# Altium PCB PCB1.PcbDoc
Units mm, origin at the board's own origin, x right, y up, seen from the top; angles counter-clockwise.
Board outline 20 x 15 mm, 2 copper layers (Top Layer, Bottom Layer); 3 components, 0 nets, 4 pads, 0 vias.
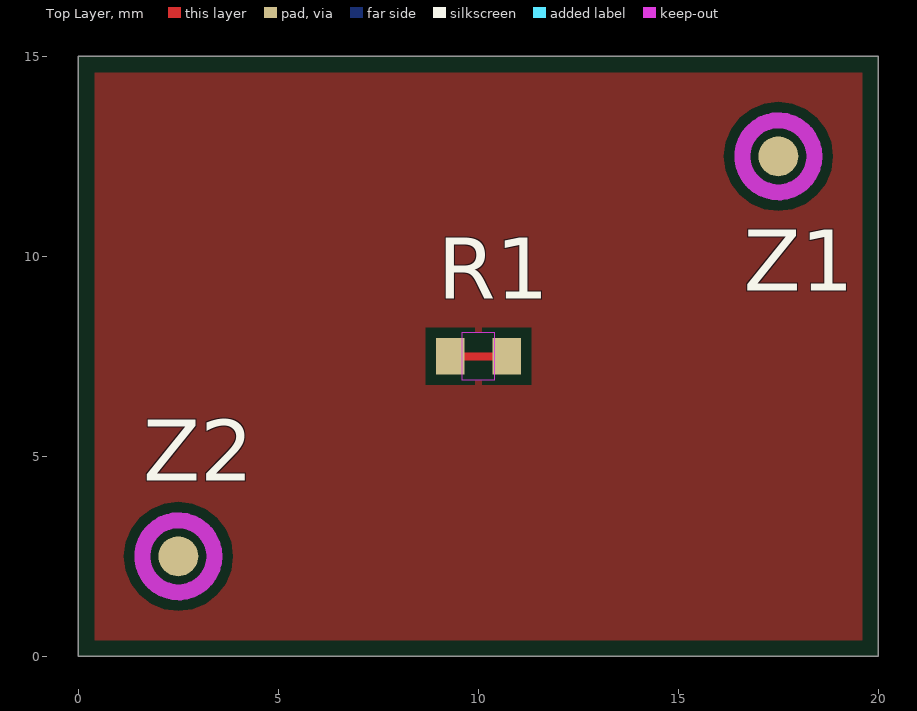
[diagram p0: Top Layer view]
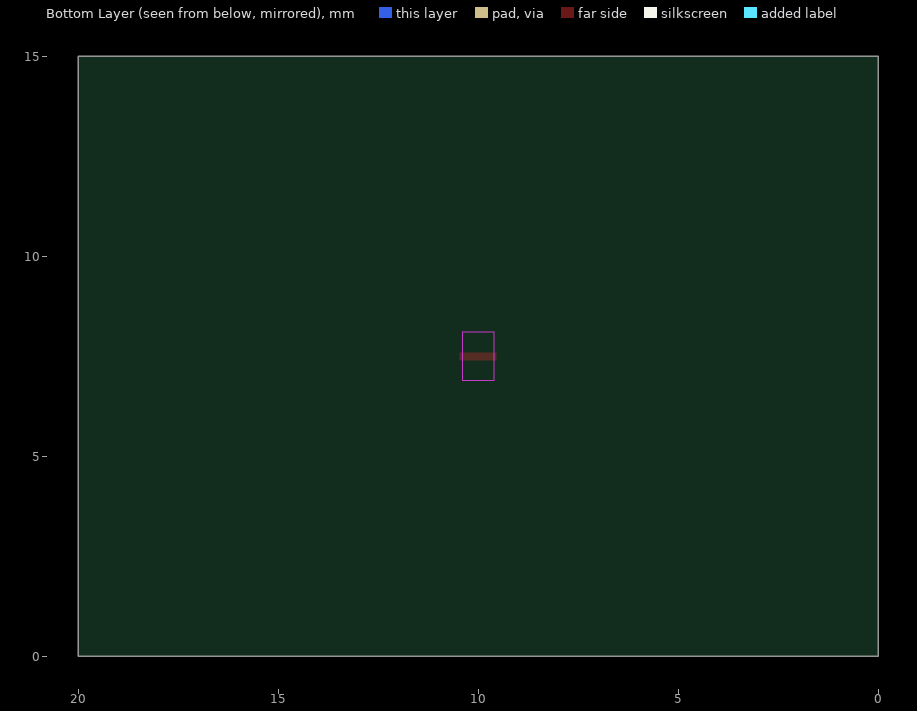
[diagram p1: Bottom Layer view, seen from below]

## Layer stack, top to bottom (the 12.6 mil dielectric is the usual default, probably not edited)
Top Solder: solder mask 0.0102, Solder Resist, Dk 3.5
Top Layer: signal copper 0.0356
Dielectric 1: dielectric 0.32, FR-4, Dk 4.8
Bottom Layer: signal copper 0.0356
Bottom Solder: solder mask 0.0102, Solder Resist, Dk 3.5

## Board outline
0,0 0,15 20,15 20,0

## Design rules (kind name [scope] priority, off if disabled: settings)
BoardOutlineClearance [All] p1: gap=0.4 ignorepadtopadclearanceinfootprint=FALSE
Clearance [All] p1: gap=0.254 ignorepadtopadclearanceinfootprint=FALSE
PolygonConnect [All] p1: connectstyle=Relief reliefconductorwidth=0.254 reliefentries=4 polygonreliefangle="90 Angle" airgapwidth=0.254
RoutingVias [All] p1: holewidth=0.711 width=1.27 viastyle="Through Hole" minholewidth=0.711 minwidth=1.27 maxholewidth=0.711 maxwidth=1.27
SolderMaskExpansion [All] p1: expansion=0.102 istentingtop=FALSE
Width [All] p1: maxlimit=0.254 minlimit=0.254 preferedwidth=0.254
30 further rules are at their usual default settings.

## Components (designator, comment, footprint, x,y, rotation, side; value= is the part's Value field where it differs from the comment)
R1 "n.b." R0603NB-0R 10,7.5 r0 top net-tie
Z1 "FIDU_R" FIDU_R 17.5,12.5 r0 top
Z2 "FIDU_R" FIDU_R 2.5,2.5 r0 top

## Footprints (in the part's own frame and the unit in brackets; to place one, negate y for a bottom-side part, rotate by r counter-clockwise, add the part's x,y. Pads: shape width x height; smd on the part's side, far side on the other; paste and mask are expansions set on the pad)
FIDU_R [mm] "Fiducial Mark d=1mm"
  round 1 smd paste-0.55 mask+0.5: 0(0,0)
  Top Layer keep-out circle w0.4: c0,0 r0.9
R0603NB-0R [mil] "nicht bestückt - Brücke"
  rect 28x36 smd paste-0.98: 1(-27.56,0) 2(28,0)
  Top Layer region: -17.72,-3.94 18.7,-3.94 18.7,3.94 -17.72,3.94
  Keep-Out Layer pour cut-out: -15.75,23.62 15.75,23.62 15.75,-23.62 -15.75,-23.62

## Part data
R1: library part N.B.-0603_0R, "n.b. nicht bestückt - Brücke"
Z1 Z2: library part FIDUCIAL_KREIS, "Fiducial rund 1mm"

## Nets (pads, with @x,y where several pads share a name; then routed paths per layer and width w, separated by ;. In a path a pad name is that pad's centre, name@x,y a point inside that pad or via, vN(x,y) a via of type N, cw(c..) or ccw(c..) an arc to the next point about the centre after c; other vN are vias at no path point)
pads on no net: R1.1 R1.2 Z1.0 Z2.0

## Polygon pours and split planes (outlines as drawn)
no net on Top Layer "NONET_L-01_P-001" (solid, pour order 0): 0,0 0,15 20,15 20,0

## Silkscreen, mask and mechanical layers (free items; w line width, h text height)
Board Shape:
  the board outline again, w0.1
